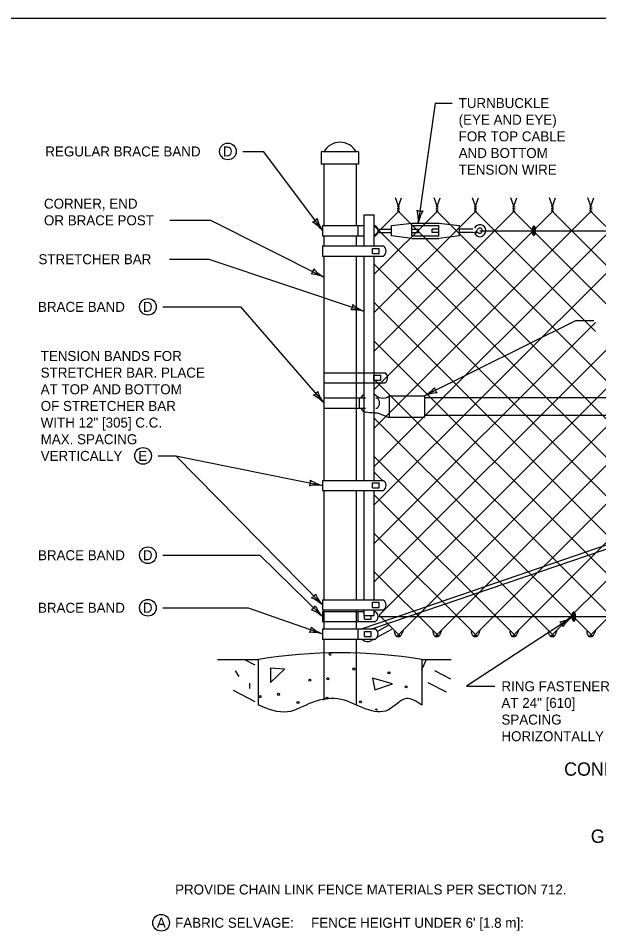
# Model space of a CAD drawing. Extents: x 49973.1 to 50021, y 49987.6 to 50015.4.
# Drawn here: x 50008.41 to 50011.89, y 49993.51 to 49999 of the extents above; entities that cross this region are included whole.
import ezdxf

# ---------------------------------------------------------------- set-up
doc = ezdxf.new("R2010")
doc.units = 0
for name, color, linetype in [('Level 1', 7, 'Continuous'), ('Level 2', 7, 'Continuous'), ('Level 3', 7, 'Continuous'), ('Level 4', 7, 'Continuous')]:
    doc.layers.add(name, color=color, linetype=linetype)

msp = doc.modelspace()

# ---------------------------------------------------------------- linework, layer by layer
at = {"layer": 'Level 1'}
for p, q in [((50010.4497, 49998.1973), (50010.2262, 49998.1973)), ((50010.2262, 49998.1973), (50010.2262, 49998.1238)), ((50010.4497, 49998.1973), (50010.4497, 49998.1238)), ((50010.4497, 49998.1238), (50010.2262, 49998.1238)), ((50010.2419, 49998.1238), (50010.2419, 49997.754)), ((50010.4359, 49998.1238), (50010.4359, 49997.754)), ((50010.69, 49997.8714), (50010.672, 49997.9209)), ((50010.69, 49997.8714), (50010.708, 49997.9209)), ((50010.9209, 49997.8714), (50010.9029, 49997.9209)), ((50010.9209, 49997.8714), (50010.939, 49997.9209)), ((50011.1514, 49997.8709), (50011.1334, 49997.9205)), ((50011.1514, 49997.8709), (50011.1695, 49997.9205)), ((50011.3824, 49997.871), (50011.3644, 49997.9205)), ((50011.3824, 49997.871), (50011.4005, 49997.9205)), ((50011.6138, 49997.8714), (50011.5957, 49997.9209)), ((50011.6138, 49997.8714), (50011.6318, 49997.9209)), ((50011.8444, 49997.8711), (50011.8264, 49997.9206)), ((50011.8444, 49997.8711), (50011.8625, 49997.9206)), ((50010.6824, 49997.87), (50010.6978, 49997.8672)), ((50010.69, 49997.8389), (50010.69, 49997.8714)), ((50010.9133, 49997.87), (50010.9288, 49997.8672)), ((50010.9209, 49997.8389), (50010.9209, 49997.8714)), ((50011.1438, 49997.8695), (50011.1593, 49997.8668)), ((50011.1514, 49997.8385), (50011.1514, 49997.8709)), ((50011.3748, 49997.8696), (50011.3903, 49997.8669)), ((50011.3824, 49997.8385), (50011.3824, 49997.871)), ((50011.6062, 49997.87), (50011.6216, 49997.8672)), ((50011.6138, 49997.8389), (50011.6138, 49997.8714)), ((50011.8368, 49997.8697), (50011.8523, 49997.867)), ((50011.8444, 49997.8386), (50011.8444, 49997.8711)), ((50010.4833, 49997.8185), (50010.5445, 49997.8185)), ((50010.4833, 49997.6323), (50010.4833, 49997.8185)), ((50010.5445, 49996.0769), (50012.3066, 49997.8389)), ((50010.5445, 49996.3078), (50012.0756, 49997.8389)), ((50010.5445, 49996.5387), (50011.8447, 49997.8389)), ((50010.5445, 49996.7697), (50011.6138, 49997.8389)), ((50010.5445, 49997.4625), (50010.9209, 49997.8389)), ((50010.5445, 49997.6934), (50010.69, 49997.8389)), ((50010.5445, 49997.0006), (50011.3824, 49997.8385)), ((50010.5445, 49997.2316), (50011.1515, 49997.8385)), ((50010.5445, 49997.6323), (50010.5445, 49997.8185)), ((50010.6824, 49997.8573), (50010.6978, 49997.8545)), ((50010.6824, 49997.8446), (50010.6978, 49997.8419)), ((50010.69, 49997.8389), (50013.2411, 49995.2878)), ((50013.4614, 49997.8389), (50010.9099, 49995.2874)), ((50010.9133, 49997.8573), (50010.9288, 49997.8545)), ((50010.9133, 49997.8446), (50010.9288, 49997.8419)), ((50010.9209, 49997.8389), (50013.4721, 49995.2878)), ((50011.1409, 49995.2873), (50013.6923, 49997.8388)), ((50011.1438, 49997.8568), (50011.1593, 49997.8541)), ((50011.1438, 49997.8441), (50011.1593, 49997.8414)), ((50011.1515, 49997.8385), (50011.8713, 49997.1187)), ((50011.3718, 49995.2873), (50013.9234, 49997.8389)), ((50011.3748, 49997.8569), (50011.3903, 49997.8542)), ((50011.3748, 49997.8442), (50011.3903, 49997.8415)), ((50011.3824, 49997.8385), (50011.9504, 49997.2705)), ((50011.6028, 49995.2873), (50014.1545, 49997.8389)), ((50011.6062, 49997.8573), (50011.6216, 49997.8545)), ((50011.6062, 49997.8446), (50011.6216, 49997.8419)), ((50011.6138, 49997.8389), (50012.1821, 49997.2705)), ((50011.8368, 49997.857), (50011.8523, 49997.8543)), ((50011.8368, 49997.8443), (50011.8523, 49997.8416)), ((50011.8447, 49997.8389), (50012.4131, 49997.2705)), ((50010.2331, 49997.754), (50010.2331, 49997.6928)), ((50010.2331, 49997.754), (50010.4833, 49997.754)), ((50010.4447, 49997.754), (50010.4447, 49997.6928)), ((50010.5445, 49997.754), (50010.5519, 49997.754)), ((50010.5445, 49997.7534), (50013.0102, 49995.2878)), ((50010.647, 49997.754), (50010.7695, 49997.7693)), ((50010.647, 49997.6928), (50010.647, 49997.754)), ((50010.7695, 49997.7693), (50010.9327, 49997.7693)), ((50010.7695, 49997.754), (50010.9327, 49997.754)), ((50010.7695, 49997.6928), (50010.7695, 49997.754)), ((50010.9327, 49997.7693), (50011.0552, 49997.754)), ((50010.9327, 49997.6928), (50010.9327, 49997.754)), ((50011.0552, 49997.6928), (50011.0552, 49997.754)), ((50010.5658, 49997.7336), (50010.647, 49997.7336)), ((50010.5658, 49997.7132), (50010.647, 49997.7132)), ((50010.7695, 49997.7336), (50010.8103, 49997.7336)), ((50010.7695, 49997.7132), (50010.8103, 49997.7132)), ((50010.8103, 49997.7132), (50010.8103, 49997.7336)), ((50010.8919, 49997.7132), (50010.8919, 49997.7336)), ((50010.9327, 49997.7336), (50010.8919, 49997.7336)), ((50010.9327, 49997.7132), (50010.8919, 49997.7132)), ((50011.1369, 49997.7336), (50011.0552, 49997.7336)), ((50011.1369, 49997.7132), (50011.0552, 49997.7132)), ((50011.1648, 49997.7157), (50011.1472, 49997.7053)), ((50011.1779, 49997.7234), (50011.5054, 49997.7234)), ((50011.5128, 49997.7234), (50011.5262, 49997.7234)), ((50011.5262, 49997.7234), (50012.8518, 49997.7234)), ((50010.2331, 49997.6928), (50010.4833, 49997.6928)), ((50010.2419, 49997.6928), (50010.2419, 49997.6323)), ((50010.4359, 49997.6928), (50010.4359, 49997.6323)), ((50010.5445, 49997.6928), (50010.5519, 49997.6928)), ((50010.7695, 49997.6775), (50010.647, 49997.6928)), ((50010.7695, 49997.6928), (50010.9327, 49997.6928)), ((50010.7695, 49997.6775), (50010.9327, 49997.6775)), ((50011.0552, 49997.6928), (50010.9327, 49997.6775)), ((50010.2331, 49997.6323), (50010.2331, 49997.5712)), ((50010.2331, 49997.6323), (50010.5998, 49997.6323)), ((50010.5335, 49997.5865), (50010.5335, 49997.617)), ((50010.5335, 49997.617), (50010.5743, 49997.617)), ((50010.5743, 49997.5865), (50010.5743, 49997.617)), ((50010.2331, 49997.5712), (50010.5998, 49997.5712)), ((50010.2419, 49997.5712), (50010.2419, 49996.2245)), ((50010.4359, 49997.5712), (50010.4359, 49996.526)), ((50010.4833, 49996.5387), (50010.4833, 49997.5712)), ((50010.5335, 49997.5865), (50010.5743, 49997.5865)), ((50010.5445, 49996.4943), (50010.5445, 49997.5712)), ((50010.5445, 49997.5225), (50012.7792, 49995.2878)), ((50011.8338, 49995.2872), (50014.0789, 49997.5324)), ((50010.5445, 49997.2915), (50012.5482, 49995.2878)), ((50010.5445, 49995.8459), (50011.8713, 49997.1727)), ((50011.8702, 49997.1716), (50011.8713, 49997.1727)), ((50011.8702, 49997.1716), (50011.8713, 49997.1727)), ((50011.8702, 49997.1198), (50011.8713, 49997.1187)), ((50011.8702, 49997.1198), (50011.8713, 49997.1187)), ((50010.5445, 49997.0606), (50012.3172, 49995.2879)), ((50010.5445, 49995.615), (50011.9357, 49997.0061)), ((50010.5745, 49995.414), (50012.1666, 49997.0061)), ((50010.6789, 49995.2874), (50012.3976, 49997.0061)), ((50010.2419, 49996.871), (50010.2419, 49996.8099)), ((50010.2419, 49996.871), (50010.6087, 49996.871)), ((50010.5423, 49996.8252), (50010.5423, 49996.8558)), ((50010.5423, 49996.8558), (50010.5831, 49996.8558)), ((50010.5423, 49996.8252), (50010.5831, 49996.8252)), ((50010.5445, 49996.8297), (50012.0863, 49995.2879)), ((50010.5831, 49996.8252), (50010.5831, 49996.8558)), ((50010.2419, 49996.8099), (50010.6087, 49996.8099)), ((50010.2419, 49996.7198), (50010.2419, 49996.6587)), ((50010.2419, 49996.7198), (50010.4921, 49996.7198)), ((50010.4535, 49996.7198), (50010.4535, 49996.6587)), ((50010.5534, 49996.7198), (50010.5607, 49996.7198)), ((50010.6336, 49996.7314), (50010.8461, 49996.7314)), ((50010.6336, 49996.7314), (50010.6336, 49996.6044)), ((50010.8461, 49996.7314), (50010.8461, 49996.6044)), ((50013.71, 49996.7209), (50010.8461, 49996.7209)), ((50010.2419, 49996.6587), (50010.4921, 49996.6587)), ((50010.5534, 49996.6587), (50010.5607, 49996.6587)), ((50010.6111, 49996.6106), (50010.5804, 49996.6225)), ((50010.6336, 49996.6044), (50010.8461, 49996.6044)), ((50013.71, 49996.6149), (50010.8461, 49996.6149)), ((50010.4359, 49996.5949), (50010.4359, 49996.4099)), ((50010.4833, 49996.2245), (50010.4833, 49996.5949)), ((50010.5445, 49996.5987), (50011.8553, 49995.2879)), ((50010.5445, 49996.2245), (50010.5445, 49996.5795)), ((50010.4359, 49996.4099), (50010.4359, 49996.2245)), ((50010.5445, 49996.3678), (50011.6243, 49995.288)), ((50010.5445, 49996.273), (50010.5931, 49996.2245)), ((50010.2331, 49996.2245), (50010.2331, 49996.1633)), ((50010.2331, 49996.2245), (50010.5998, 49996.2245)), ((50013.1116, 49996.2399), (50010.647, 49995.3928)), ((50010.2331, 49996.1633), (50010.5998, 49996.1633)), ((50010.2419, 49996.1633), (50010.2419, 49995.5073)), ((50010.4359, 49996.1633), (50010.4359, 49995.5073)), ((50010.4833, 49995.5073), (50010.4833, 49996.1633)), ((50010.5335, 49996.1786), (50010.5335, 49996.2092)), ((50010.5335, 49996.2092), (50010.5743, 49996.2092)), ((50010.5335, 49996.1786), (50010.5743, 49996.1786)), ((50010.5445, 49995.5073), (50010.5445, 49996.1633)), ((50010.5743, 49996.1786), (50010.5743, 49996.2092)), ((50010.6541, 49995.3752), (50013.1204, 49996.2141)), ((50010.5445, 49996.1368), (50011.3933, 49995.288)), ((50010.5445, 49995.9059), (50011.1624, 49995.2881)), ((50010.5445, 49995.6749), (50010.9314, 49995.2881)), ((50010.2331, 49995.5073), (50010.2331, 49995.4461)), ((50010.2331, 49995.5073), (50010.5998, 49995.5073)), ((50010.5335, 49995.4614), (50010.5335, 49995.492)), ((50010.5335, 49995.492), (50010.5743, 49995.492)), ((50010.5335, 49995.4614), (50010.5743, 49995.4614)), ((50010.5743, 49995.4614), (50010.5743, 49995.492)), ((50010.2331, 49995.4461), (50010.5998, 49995.4461)), ((50010.2331, 49995.4372), (50010.4833, 49995.4372)), ((50010.2331, 49995.4372), (50010.2331, 49995.3761)), ((50010.2419, 49995.4461), (50010.2419, 49995.3326)), ((50010.4359, 49995.4461), (50010.4359, 49995.3326)), ((50010.4447, 49995.4372), (50010.4447, 49995.3761)), ((50010.647, 49995.3928), (50010.4717, 49995.3326)), ((50010.4833, 49995.4125), (50010.4833, 49995.4461)), ((50010.4833, 49995.4125), (50010.5445, 49995.4125)), ((50010.4855, 49995.3913), (50010.4855, 49995.4125)), ((50010.4855, 49995.3913), (50010.4855, 49995.4125)), ((50010.5263, 49995.3913), (50010.5263, 49995.4125)), ((50010.5263, 49995.3913), (50010.5263, 49995.4125)), ((50010.5445, 49995.4125), (50010.5445, 49995.4461)), ((50010.5445, 49995.4372), (50010.5519, 49995.4372)), ((50010.5672, 49995.4066), (50011.7451, 49995.4066)), ((50010.5745, 49995.414), (50010.7004, 49995.2881)), ((50011.7524, 49995.4066), (50012.926, 49995.4066)), ((50010.2331, 49995.3761), (50010.5519, 49995.3761)), ((50010.4855, 49995.3913), (50010.5263, 49995.3913)), ((50010.4855, 49995.3913), (50010.5263, 49995.3913)), ((50010.5291, 49995.3326), (50010.6541, 49995.3752)), ((50010.6297, 49995.3546), (50010.564, 49995.3174)), ((50010.2331, 49995.3326), (50010.2331, 49995.2715)), ((50010.2331, 49995.3326), (50010.5519, 49995.3326)), ((50010.4447, 49995.3326), (50010.4447, 49995.2715)), ((50010.4855, 49995.2868), (50010.4855, 49995.3173)), ((50010.4855, 49995.3173), (50010.5263, 49995.3173)), ((50010.4855, 49995.2868), (50010.5263, 49995.2868)), ((50010.5263, 49995.2868), (50010.5263, 49995.3173)), ((50010.6469, 49995.3292), (50010.5603, 49995.2801)), ((50010.2331, 49995.2715), (50010.5519, 49995.2715)), ((50010.2419, 49995.2715), (50010.2419, 49995.1876)), ((50010.4359, 49995.2715), (50010.4359, 49995.1876)), ((50010.545, 49995.2715), (50010.5285, 49995.2621)), ((50009.6039, 49995.1483), (50009.8489, 49995.1483)), ((50009.8297, 49995.1137), (50009.7641, 49995.1483)), ((50009.8489, 49994.8748), (50009.8489, 49995.1483)), ((50010.8289, 49995.1483), (50010.8289, 49994.8748)), ((50010.8289, 49995.0889), (50010.8587, 49995.1483)), ((50010.8289, 49995.1483), (50011.0055, 49995.1483)), ((50009.7327, 49995.0457), (50009.7107, 49995.0798)), ((50009.9205, 49995.0957), (50009.9205, 49995.0107)), ((50010.0055, 49995.0913), (50009.9205, 49995.0957)), ((50009.9205, 49995.0107), (50010.0055, 49995.0913)), ((50011.0029, 49995.0307), (50010.9071, 49995.0807)), ((50010.5336, 49995.0375), (50010.547, 49994.9659)), ((50010.6545, 49995.0018), (50010.5336, 49995.0375)), ((50010.9779, 49994.9521), (50010.8687, 49995.0095)), ((50009.8287, 49994.8944), (50009.6986, 49994.9623)), ((50009.7977, 49994.9751), (50009.7977, 49995.0067)), ((50010.547, 49994.9659), (50010.6545, 49995.0018))]:
    msp.add_line(p, q, dxfattribs=at)
msp.add_lwpolyline([(49999.3835, 49998.9992), (50016.7501, 49998.9992), (50016.7501, 49987.7988), (49999.3835, 49987.7988)], close=True, dxfattribs=at)
for centre in [(50010.4218, 49995.0914), (50010.6323, 49995.069), (50010.1578, 49995.0243), (50010.2652, 49995.0332), (50010.7352, 49994.9841), (50009.8579, 49994.9259), (50009.9697, 49994.9392), (50010.2607, 49994.9169), (50010.462, 49994.8945), (50010.0862, 49994.89)]:
    msp.add_circle(centre, 0.00629, dxfattribs=at)
for centre, radius, start, end in [((50010.3389, 49998.1435), 0.1108, 28.8965, 151.1035), ((50010.529, 49997.7234), 0.0382, 306.8699, 53.1301), ((50011.1779, 49997.7234), 0.0357, 210.935, 153.6122), ((50011.1369, 49997.7438), 0.0306, 270, 333.6122), ((50011.1779, 49997.7234), 0.0153, 210.2657, 153.6122), ((50010.5769, 49997.6017), 0.0382, 306.8699, 53.1301), ((50010.5857, 49996.8405), 0.0382, 306.8699, 53.1301), ((50010.5147, 49996.6893), 0.0605, 121.3345, 149.6397), ((50010.5957, 49996.7817), 0.063, 215.6928, 307.0302), ((50010.5378, 49996.6893), 0.0382, 306.8699, 53.1301), ((50010.5147, 49996.6893), 0.0605, 210.3603, 245.3903), ((50010.2553, 49996.0921), 0.5906, 66.3593, 66.6293), ((50010.4004, 49995.6087), 1.0287, 81.9459, 84.9066), ((50010.5552, 49996.5701), 0.0582, 64.3202, 100.5294), ((50010.6317, 49996.6414), 0.0371, 236.2005, 272.9911), ((50010.5769, 49996.1939), 0.0382, 306.8699, 53.1301), ((50010.5769, 49995.4767), 0.0382, 306.8699, 53.1301), ((50010.529, 49995.4066), 0.0382, 306.8699, 53.1301), ((50010.529, 49995.302), 0.0382, 306.8699, 53.1301), ((50010.5059, 49995.302), 0.0459, 221.8103, 299.5338), ((50010.3389, 49992.2381), 2.9511, 80.4434, 99.5566), ((50010.2786, 49995.1809), 0.00629, 144.298, 45.4773), ((50010.5561, 49994.8435), 0.00629, 354.1497, 172.0914)]:
    msp.add_arc(centre, radius, start, end, dxfattribs=at)
for centre, major_axis, ratio, start_param, end_param in [((50011.502, 49997.7234), (0.0004, -0.0279), 0.383232, 4.86378, 10.729979), ((50011.4952, 49997.7297), (-0.00355, 0.00095), 0.282483, 0.154702, 3.14159), ((50011.502, 49997.7234), (0.0003, -0.0206), 0.163161, 4.86378, 10.729979), ((50011.7417, 49995.4066), (0.0004, -0.0279), 0.383232, 4.86378, 10.729979), ((50011.7348, 49995.4129), (-0.00355, 0.00095), 0.282483, 0.154702, 3.14159), ((50011.7417, 49995.4066), (0.0003, -0.0206), 0.163161, 4.86378, 10.729979)]:
    msp.add_ellipse(centre, major_axis=major_axis, ratio=ratio, start_param=start_param, end_param=end_param, dxfattribs=at)
for centre in [(50011.4951, 49997.7196), (50011.7348, 49995.4029)]:
    msp.add_ellipse(centre, major_axis=(-0.00362, -0.0006), ratio=0.282483, dxfattribs=at)
for points in [[(50010.69, 49995.2985), (50010.6949, 49995.2928), (50010.6931, 49995.2873), (50010.6851, 49995.2842), (50010.6729, 49995.2946), (50010.6655, 49995.3172)], [(50010.69, 49995.2985), (50010.6863, 49995.2916), (50010.6894, 49995.2861), (50010.7022, 49995.2903), (50010.7114, 49995.3068), (50010.7187, 49995.3221)], [(50010.921, 49995.2985), (50010.9259, 49995.2927), (50010.924, 49995.2872), (50010.9161, 49995.2842), (50010.9039, 49995.2946), (50010.8965, 49995.3172)], [(50010.921, 49995.2985), (50010.9173, 49995.2915), (50010.9204, 49995.286), (50010.9332, 49995.2903), (50010.9424, 49995.3068), (50010.9497, 49995.3221)], [(50011.152, 49995.2984), (50011.1568, 49995.2927), (50011.155, 49995.2872), (50011.1471, 49995.2842), (50011.1348, 49995.2945), (50011.1275, 49995.3172)], [(50011.152, 49995.2984), (50011.1483, 49995.2915), (50011.1513, 49995.286), (50011.1642, 49995.2903), (50011.1734, 49995.3068), (50011.1807, 49995.322)], [(50011.383, 49995.2984), (50011.3878, 49995.2927), (50011.386, 49995.2872), (50011.378, 49995.2841), (50011.3658, 49995.2945), (50011.3585, 49995.3171)], [(50011.383, 49995.2984), (50011.3793, 49995.2915), (50011.3823, 49995.286), (50011.3952, 49995.2902), (50011.4043, 49995.3067), (50011.4117, 49995.322)], [(50011.6139, 49995.2984), (50011.6188, 49995.2926), (50011.617, 49995.2871), (50011.609, 49995.2841), (50011.5968, 49995.2945), (50011.5894, 49995.3171)], [(50011.6139, 49995.2984), (50011.6102, 49995.2914), (50011.6133, 49995.2859), (50011.6261, 49995.2902), (50011.6353, 49995.3067), (50011.6426, 49995.322)], [(50011.8449, 49995.2983), (50011.8498, 49995.2926), (50011.8479, 49995.2871), (50011.84, 49995.284), (50011.8278, 49995.2944), (50011.8204, 49995.3171)], [(50011.8449, 49995.2983), (50011.8412, 49995.2914), (50011.8443, 49995.2859), (50011.8571, 49995.2902), (50011.8663, 49995.3067), (50011.8736, 49995.3219)], [(50010.8289, 49994.8748), (50010.7374, 49994.9145), (50010.628, 49994.8453), (50010.4955, 49994.8511), (50010.3458, 49994.9087), (50010.1731, 49994.8914), (50010.0234, 49994.8338), (50009.8489, 49994.8748)]]:
    msp.add_spline(points, degree=3, dxfattribs=at)
at = {"layer": 'Level 2'}
for centre in [(50009.6656, 49998.1996), (50009.1856, 49997.2664), (50009.1561, 49996.3714), (50009.1856, 49995.7748), (50009.1856, 49995.4592), (50009.2648, 49993.5675)]:
    msp.add_circle(centre, 0.05, dxfattribs=at)
at = {"layer": 'Level 3'}
for p, q in [((50010.91, 49998.4901), (50010.8084, 49997.7693)), ((50010.91, 49998.4901), (50011.0109, 49998.4901)), ((50009.7556, 49998.1996), (50009.8772, 49998.1996)), ((50009.8772, 49998.1996), (50010.2331, 49997.7252)), ((50009.3175, 49997.7859), (50009.5611, 49997.7859)), ((50009.5606, 49997.7859), (50010.2419, 49997.4448)), ((50009.3156, 49997.5524), (50009.5514, 49997.5524)), ((50009.5514, 49997.5524), (50010.4833, 49997.2396)), ((50009.2756, 49997.2664), (50009.7421, 49997.2664)), ((50009.7421, 49997.2664), (50010.2419, 49996.6893)), ((50011.7567, 49997.1846), (50010.8461, 49996.7314)), ((50011.7567, 49997.1846), (50011.8627, 49997.1846)), ((50009.2461, 49996.3714), (50009.3526, 49996.3714)), ((50009.3526, 49996.3714), (50010.2331, 49996.1939)), ((50009.3526, 49996.3714), (50010.2331, 49995.4767)), ((50009.2756, 49995.7748), (50009.8565, 49995.7748)), ((50009.8565, 49995.7748), (50010.2331, 49995.4066)), ((50009.2757, 49995.4592), (50009.7877, 49995.4592)), ((50009.7877, 49995.4592), (50010.2331, 49995.302)), ((50011.7312, 49995.4023), (50011.0977, 49994.9879)), ((50011.0977, 49994.9879), (50011.2677, 49994.9879))]:
    msp.add_line(p, q, dxfattribs=at)
for centre, radius, start, end in [((50010.8263, 49997.8962), 0.0548, 244.1162, 279.8386), ((50010.5764, 49997.7904), 0.233, 354.8047, 14.0546), ((50011.0271, 49997.7292), 0.2223, 149.4334, 169.6169), ((50010.1562, 49997.8278), 0.0548, 288.9769, 324.6992), ((50010.0538, 49997.5764), 0.233, 39.6654, 58.9152), ((50010.4164, 49997.851), 0.2223, 194.2941, 214.4776), ((50010.1273, 49997.5022), 0.0548, 315.5414, 351.2637), ((50010.3496, 49997.6393), 0.2223, 220.8586, 241.0421), ((50010.148, 49997.2315), 0.233, 66.2299, 85.4797), ((50010.3617, 49997.2804), 0.0548, 323.5832, 359.3056), ((50010.5627, 49997.4472), 0.2223, 228.9004, 249.0839), ((50010.4201, 49997.0153), 0.233, 74.2717, 93.5216), ((50010.7321, 49996.9346), 0.233, 299.2862, 318.536), ((50010.9609, 49996.7885), 0.0548, 188.5977, 224.32), ((50010.1578, 49996.786), 0.0548, 293.1349, 328.8572), ((50010.0738, 49996.5279), 0.233, 43.8233, 63.0732), ((50010.4156, 49996.8281), 0.2223, 198.452, 218.6356), ((50010.9369, 49996.5284), 0.2223, 93.9149, 114.0984), ((50010.1075, 49996.2192), 0.0548, 330.7445, 6.4669), ((50010.286, 49996.4098), 0.2223, 236.0617, 256.2452), ((50010.1984, 49995.9635), 0.233, 81.433, 100.6829), ((50010.1432, 49995.5681), 0.0548, 296.6952, 332.4175), ((50010.0754, 49995.3052), 0.233, 47.3837, 66.6335), ((50010.3978, 49995.626), 0.2223, 202.0124, 222.1959), ((50010.1413, 49995.4961), 0.0548, 297.911, 333.6333), ((50010.0791, 49995.2319), 0.233, 48.5995, 67.8493), ((50010.3946, 49995.5594), 0.2223, 203.2282, 223.4117), ((50011.6172, 49995.5932), 0.2223, 280.6591, 300.8426), ((50011.8682, 49995.2139), 0.233, 126.0304, 145.2803), ((50010.1122, 49995.3447), 0.0548, 322.7104, 358.4328), ((50010.3156, 49995.5085), 0.2223, 228.0276, 248.2111), ((50011.6239, 49995.3321), 0.0548, 15.3419, 51.0643), ((50010.1666, 49995.0788), 0.233, 73.3989, 92.6487)]:
    msp.add_arc(centre, radius, start, end, dxfattribs=at)
at = {"layer": 'Level 4'}
for p, q in [((50010.2419, 49995.1876), (50010.2419, 49994.9039)), ((50010.4359, 49995.1876), (50010.4359, 49994.8759))]:
    msp.add_line(p, q, dxfattribs=at)

# ---------------------------------------------------------------- texts
at = {"layer": 'Level 2'}
for s, height, p in [('TURNBUCKLE', 0.06, (50011.0509, 49998.4601)), ('(EYE AND EYE)', 0.06, (50011.0509, 49998.3601)), ('FOR TOP CABLE', 0.06, (50011.0509, 49998.2601)), ('REGULAR BRACE BAND', 0.06, (50008.5697, 49998.1696)), ('D', 0.06, (50009.6353, 49998.1696)), ('AND BOTTOM', 0.06, (50011.0509, 49998.1601)), ('TENSION WIRE', 0.06, (50011.0509, 49998.0601)), ('CORNER, END', 0.06, (50008.5617, 49997.8559)), ('OR BRACE POST', 0.06, (50008.5617, 49997.7559)), ('STRETCHER BAR', 0.06, (50008.5285, 49997.5224)), ('BRACE BAND', 0.06, (50008.5257, 49997.2364)), ('D', 0.06, (50009.1553, 49997.2364)), ('TENSION BANDS FOR', 0.06, (50008.542, 49996.9414)), ('STRETCHER BAR. PLACE', 0.06, (50008.542, 49996.8414)), ('AT TOP AND BOTTOM', 0.06, (50008.542, 49996.7414)), ('OF STRETCHER BAR', 0.06, (50008.542, 49996.6414)), ('WITH 12" [305] C.C.', 0.06, (50008.542, 49996.5414)), ('MAX. SPACING', 0.06, (50008.542, 49996.4414)), ('VERTICALLY', 0.06, (50008.542, 49996.3414)), ('E', 0.06, (50009.1281, 49996.3414)), ('BRACE BAND', 0.06, (50008.5257, 49995.7448)), ('D', 0.06, (50009.1553, 49995.7448)), ('BRACE BAND', 0.06, (50008.5257, 49995.4292)), ('D', 0.06, (50009.1553, 49995.4292)), ('RING FASTENER', 0.06, (50011.3077, 49994.9579)), ('AT 24" [610]', 0.06, (50011.3077, 49994.8579)), ('SPACING', 0.06, (50011.3077, 49994.7579)), ('HORIZONTALLY', 0.06, (50011.3077, 49994.6579)), ('CONNECTION DETAILS', 0.08, (50011.6841, 49994.4507)), ('GENERAL NOTES', 0.08, (50011.8441, 49994.0475)), ('PROVIDE CHAIN LINK FENCE MATERIALS PER SECTION 712.', 0.06, (50009.3487, 49993.7375)), ('A', 0.06, (50009.2391, 49993.5375)), ('FABRIC SELVAGE:', 0.06, (50009.3487, 49993.5375)), (" FENCE HEIGHT UNDER 6' [1.8 m]: ", 0.06, (50010.143, 49993.5375))]:
    msp.add_text(s, height=height, dxfattribs=at).set_placement(p)

doc.saveas('drawing.dxf')
